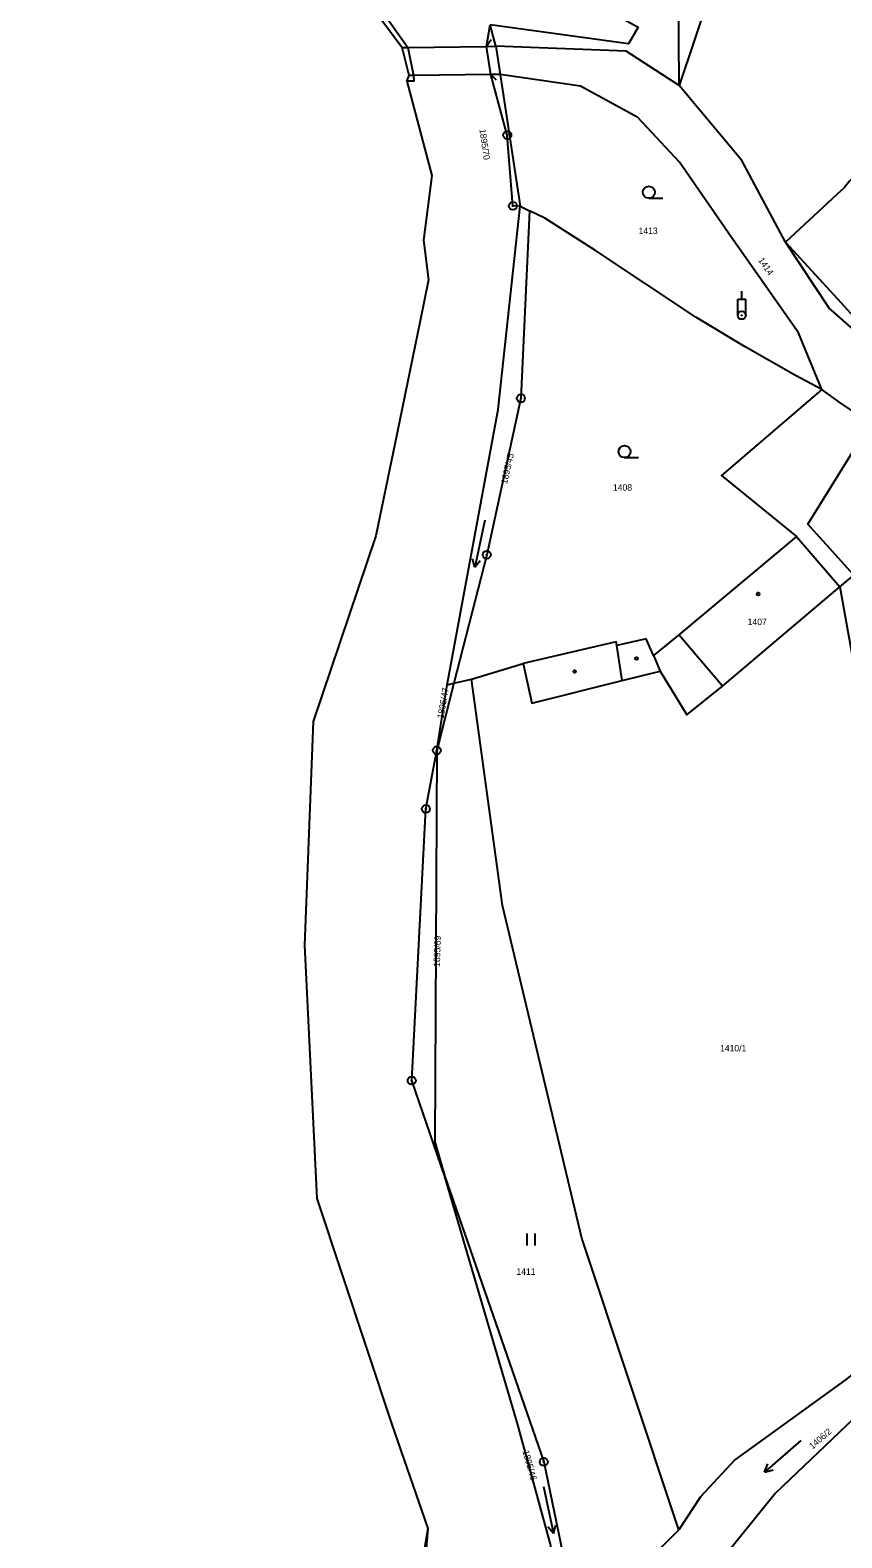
# Model space of a CAD drawing. Extents: x -587171 to -555306, y -1167727 to -1074732.
# Drawn here: x -560001.5 to -559900.1, y -1076275.6 to -1076087.4 of the extents above; entities that cross this region are included whole.
import ezdxf

# ---------------------------------------------------------------- set-up
doc = ezdxf.new("R2010")
doc.units = 0
for name, color, linetype in [('Hranice parcel', 7, 'Continuous'), ('Parcelní čísla', 7, 'Continuous'), ('Poz předměty', 7, 'Continuous'), ('Vnitřní kresba', 7, 'Continuous'), ('Značky bodu BP', 7, 'Continuous'), ('Značky budov', 7, 'Continuous'), ('Značky kultur', 7, 'Continuous')]:
    doc.layers.add(name, color=color, linetype=linetype)

msp = doc.modelspace()

# ---------------------------------------------------------------- linework, layer by layer
at = {"layer": 'Hranice parcel'}
for p, q in [((-559909.27, -1076060.92), (-559920.44, -1076094.3)), ((-559944.48, -1076089.42), (-559944.02, -1076086.75)), ((-559943.33, -1076089.41), (-559944.02, -1076086.75)), ((-559954.34, -1076089.54), (-559953.61, -1076093.04)), ((-559943.96, -1076092.94), (-559944.48, -1076089.42)), ((-559943.33, -1076089.41), (-559942.78, -1076092.93)), ((-559954.43, -1076093.78), (-559951.31, -1076105.52)), ((-559942.78, -1076092.93), (-559940.3, -1076109.37)), ((-559940.3, -1076109.37), (-559939.15, -1076109.94)), ((-559952.78, -1076123.67), (-559955.67, -1076137.64)), ((-559955.67, -1076137.64), (-559958.33, -1076150.52)), ((-559958.33, -1076150.52), (-559966.16, -1076173.69)), ((-559946.36, -1076168.41), (-559939.94, -1076166.44)), ((-559948.56, -1076168.92), (-559950.7, -1076177.29)), ((-559950.7, -1076177.29), (-559949.4, -1076169.11)), ((-559949.4, -1076169.11), (-559948.56, -1076168.92)), ((-559948.56, -1076168.92), (-559946.36, -1076168.41)), ((-559966.16, -1076173.69), (-559967.24, -1076201.59)), ((-559967.24, -1076201.59), (-559965.7, -1076233.24)), ((-559965.7, -1076233.24), (-559956.31, -1076261.44)), ((-559956.31, -1076261.44), (-559951.82, -1076274.41))]:
    msp.add_line(p, q, dxfattribs=at)
for points in [[(-559909.27, -1076060.92), (-559917.28, -1076057.19), (-559930.29, -1076053.53), (-559941.57, -1076050.67), (-559939.76, -1076079.22), (-559925.57, -1076087.03), (-559926.75, -1076089.09), (-559944.02, -1076086.75)], [(-559920.44, -1076094.3), (-559920.56, -1076076.11), (-559918.23, -1076068.13), (-559918.89, -1076062.71), (-559909.27, -1076060.92)], [(-559964.77, -1076073.74), (-559959.41, -1076080.84), (-559956.94, -1076085.86), (-559954.34, -1076089.54)], [(-559964.77, -1076073.74), (-559961.8, -1076080.39), (-559955.02, -1076089.55)], [(-559954.43, -1076093.78), (-559954.17, -1076093.05), (-559955.02, -1076089.55)], [(-559920.44, -1076094.3), (-559927.07, -1076090), (-559943.33, -1076089.41)], [(-559884.99, -1076091.09), (-559899.17, -1076106.24), (-559899.82, -1076107.06), (-559900.76, -1076107.92), (-559907.17, -1076113.84)], [(-559953.61, -1076093.04), (-559953.57, -1076093.75), (-559954.43, -1076093.78)], [(-559940.3, -1076109.37), (-559941.21, -1076109.34), (-559941.9, -1076100.49), (-559943.96, -1076092.94)], [(-559902.61, -1076132.23), (-559905.53, -1076125.19), (-559913.97, -1076113.14), (-559920.39, -1076103.88), (-559925.61, -1076098.28), (-559932.76, -1076094.38), (-559942.78, -1076092.93)], [(-559907.17, -1076113.84), (-559912.61, -1076103.65), (-559920.44, -1076094.3)], [(-559951.31, -1076105.52), (-559952.38, -1076113.61), (-559951.73, -1076118.58), (-559952.78, -1076123.67)], [(-559949.4, -1076169.11), (-559943.04, -1076134.76), (-559940.3, -1076109.37)], [(-559939.15, -1076109.94), (-559940.2, -1076133.35), (-559944.47, -1076152.87), (-559948.56, -1076168.92)], [(-559902.61, -1076132.23), (-559905.93, -1076130.5), (-559912.2, -1076126.94), (-559918.36, -1076123.2), (-559930.89, -1076114.91), (-559937.23, -1076110.88), (-559939.15, -1076109.94)], [(-559897.21, -1076126.04), (-559901.72, -1076122.11), (-559907.17, -1076113.84)], [(-559902.61, -1076132.23), (-559915.15, -1076142.97), (-559905.79, -1076150.61), (-559920.5, -1076162.86), (-559923.64, -1076165.47), (-559924.55, -1076163.38), (-559928.22, -1076164.21), (-559928.3, -1076163.76), (-559939.94, -1076166.44)], [(-559896.56, -1076136.45), (-559900.38, -1076133.87), (-559902.61, -1076132.23)], [(-559900.38, -1076156.9), (-559898.63, -1076155.42), (-559904.38, -1076149.06), (-559896.56, -1076136.45)], [(-559939.94, -1076166.44), (-559938.83, -1076171.42), (-559927.55, -1076168.59), (-559922.81, -1076167.41), (-559919.48, -1076172.87), (-559915.02, -1076169.26), (-559900.38, -1076156.9)], [(-559900.38, -1076156.9), (-559890.01, -1076214.69), (-559884, -1076224.4)], [(-559920.49, -1076274.6), (-559932.58, -1076238.17), (-559942.49, -1076196.64), (-559946.36, -1076168.41)], [(-559949.69, -1076230.48), (-559953.84, -1076218.51), (-559952.07, -1076184.6), (-559950.7, -1076177.29)], [(-559950.7, -1076177.29), (-559950.96, -1076226.17), (-559949.69, -1076230.48)], [(-559938.14, -1076296.86), (-559936.48, -1076276.53), (-559940.59, -1076261.46), (-559949.69, -1076230.48)], [(-559949.69, -1076230.48), (-559937.35, -1076266.11), (-559934.74, -1076278.57), (-559935.47, -1076287.38), (-559938.14, -1076296.86)], [(-559893.96, -1076251.31), (-559899.66, -1076255.86), (-559913.49, -1076265.83), (-559917.76, -1076270.46), (-559920.49, -1076274.6)], [(-559893.84, -1076256.62), (-559897.8, -1076259.91), (-559908.43, -1076269.99), (-559917.53, -1076281.27)], [(-559951.82, -1076274.41), (-559953.57, -1076295.85), (-559969.57, -1076322.18), (-559997.77, -1076355.74), (-560001.48, -1076359.08)], [(-559951.82, -1076274.41), (-559955.34, -1076294.95), (-559965.27, -1076313.98)], [(-559945.85, -1076321.37), (-559934.9, -1076294.34), (-559924.91, -1076278.98), (-559920.49, -1076274.6)]]:
    msp.add_lwpolyline(points, dxfattribs=at)
at = {"layer": 'Poz předměty'}
for p, q in [((-559912.63, -1076120.99), (-559912.63, -1076119.99)), ((-559913.13, -1076120.99), (-559912.13, -1076120.99)), ((-559913.13, -1076122.99), (-559913.13, -1076120.99)), ((-559912.13, -1076122.99), (-559912.13, -1076120.99))]:
    msp.add_line(p, q, dxfattribs=at)
for radius in [0.5, 0.0303]:
    msp.add_circle((-559912.63, -1076122.99), radius, dxfattribs=at)
at = {"layer": 'Vnitřní kresba'}
for p, q in [((-559943.92, -1076088.59), (-559944.48, -1076089.42)), ((-559955.02, -1076089.55), (-559954.34, -1076089.54)), ((-559954.34, -1076089.54), (-559944.48, -1076089.42)), ((-559944.48, -1076089.42), (-559943.33, -1076089.41)), ((-559953.61, -1076093.04), (-559954.17, -1076093.05)), ((-559943.96, -1076092.94), (-559953.61, -1076093.04)), ((-559942.78, -1076092.93), (-559943.96, -1076092.94)), ((-559943.25, -1076093.65), (-559943.96, -1076092.94)), ((-559907.17, -1076113.84), (-559900.69, -1076120.95)), ((-559900.69, -1076120.95), (-559896.61, -1076125.44)), ((-559905.79, -1076150.61), (-559900.38, -1076156.9)), ((-559915.02, -1076169.26), (-559920.5, -1076162.86)), ((-559927.55, -1076168.59), (-559928.22, -1076164.21)), ((-559923.64, -1076165.47), (-559922.81, -1076167.41))]:
    msp.add_line(p, q, dxfattribs=at)
at = {"layer": 'Značky bodu BP'}
for centre, radius in [((-559941.9, -1076100.49), 0.5), ((-559941.9, -1076100.49), 0.0303), ((-559941.21, -1076109.34), 0.5), ((-559941.21, -1076109.34), 0.0303), ((-559940.2, -1076133.35), 0.5), ((-559940.2, -1076133.35), 0.0303), ((-559944.47, -1076152.87), 0.5), ((-559944.47, -1076152.87), 0.0303), ((-559950.7, -1076177.29), 0.5), ((-559950.7, -1076177.29), 0.0303), ((-559952.07, -1076184.6), 0.5), ((-559952.07, -1076184.6), 0.0303), ((-559953.84, -1076218.51), 0.5), ((-559953.84, -1076218.51), 0.0303), ((-559937.35, -1076266.11), 0.5), ((-559937.35, -1076266.11), 0.0303)]:
    msp.add_circle(centre, radius, dxfattribs=at)
at = {"layer": 'Značky budov'}
for centre in [(-559910.59, -1076157.78), (-559925.77, -1076165.83), (-559933.49, -1076167.45)]:
    msp.add_circle(centre, 0.175, dxfattribs=at)
at = {"layer": 'Značky kultur'}
for p, q in [((-559924.23, -1076108.38), (-559922.48, -1076108.38)), ((-559927.26, -1076140.75), (-559925.51, -1076140.75)), ((-559944.72, -1076148.57), (-559945.97, -1076154.44)), ((-559945.97, -1076154.44), (-559946.25, -1076153.38)), ((-559945.97, -1076154.44), (-559945.27, -1076153.59)), ((-559939.42, -1076239.11), (-559939.42, -1076237.61)), ((-559938.42, -1076239.11), (-559938.42, -1076237.61)), ((-559905.25, -1076263.44), (-559909.78, -1076267.37)), ((-559909.78, -1076267.37), (-559909.37, -1076266.35)), ((-559909.78, -1076267.37), (-559908.72, -1076267.11)), ((-559937.4, -1076269.19), (-559936.15, -1076275.06)), ((-559936.15, -1076275.06), (-559936.84, -1076274.21)), ((-559936.15, -1076275.06), (-559935.86, -1076274))]:
    msp.add_line(p, q, dxfattribs=at)
for centre in [(-559924.23, -1076107.63), (-559927.26, -1076140)]:
    msp.add_circle(centre, 0.75, dxfattribs=at)

# ---------------------------------------------------------------- texts
at = {"layer": 'Parcelní čísla'}
for s, rotation, p in [('1895/70', 278, (-559945.39, -1076099.79)), ('1414', 305, (-559910.62, -1076116.12)), ('1895/45', 77, (-559941.94, -1076144.09)), ('1895/47', 80, (-559949.87, -1076173.38)), ('1895/69', 88, (-559950.32, -1076204.32)), ('1406/2', 41, (-559903.8, -1076264.58)), ('1895/46', 286, (-559940.02, -1076264.77))]:
    msp.add_text(s, height=0.803, rotation=rotation, dxfattribs=at).set_placement(p)
for s, p in [('1413', (-559925.51, -1076112.84)), ('1408', (-559928.71, -1076144.87)), ('1407', (-559911.89, -1076161.65)), ('1410/1', (-559915.34, -1076214.87)), ('1411', (-559940.77, -1076242.76))]:
    msp.add_text(s, height=0.803, dxfattribs=at).set_placement(p)

doc.saveas('drawing.dxf')
